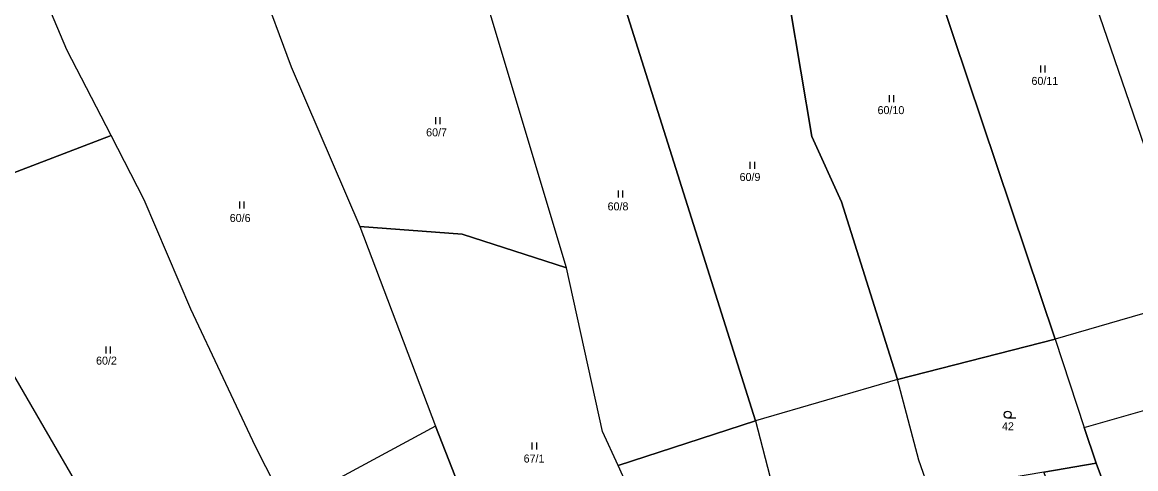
# Model space of a CAD drawing. Extents: x -590606 to -587796, y -1065936 to -1062515.
# Drawn here: x -588986.8 to -588750.2, y -1063771.4 to -1063676.6 of the extents above; entities that cross this region are included whole.
import ezdxf

# ---------------------------------------------------------------- set-up
doc = ezdxf.new("R2010")
doc.units = 0
doc.layers.add('Parcela nároku', color=7, linetype='Continuous')
doc.layers.add('Vrstva 30', color=7, linetype='Continuous')

msp = doc.modelspace()

# ---------------------------------------------------------------- linework, layer by layer
at = {"layer": 'Parcela nároku'}
for points in [[(-588715.88, -1063703.75), (-588717.17, -1063701.02), (-588727.07, -1063668.38), (-588735.7, -1063635.44), (-588736.61, -1063632.84), (-588745.65, -1063607.09), (-588774.83, -1063620.01), (-588765.6, -1063642.45), (-588759.52, -1063670.62), (-588737.36, -1063735.2), (-588707.2, -1063726.47), (-588707.58, -1063725.52)], [(-588759.52, -1063670.62), (-588737.36, -1063735.2), (-588767.37, -1063743.88), (-588804.55, -1063633.17), (-588774.83, -1063620.01), (-588765.6, -1063642.45)], [(-588804.55, -1063633.17), (-588767.37, -1063743.88), (-588800.86, -1063752.46), (-588812.73, -1063714.74), (-588819.04, -1063700.9), (-588823.74, -1063673.11), (-588832.46, -1063645.53)], [(-588819.04, -1063700.9), (-588812.73, -1063714.74), (-588800.86, -1063752.46), (-588831.03, -1063761.24), (-588863.26, -1063659.16), (-588832.46, -1063645.53), (-588823.74, -1063673.11)], [(-588889.43, -1063667.78), (-588894.21, -1063655.69), (-588891.16, -1063668.92), (-588910.08, -1063673.49), (-588936.37, -1063667.89), (-588929.67, -1063686.07), (-588915.05, -1063719.98), (-588893.31, -1063721.6), (-588871.15, -1063728.75), (-588888.64, -1063670.4)], [(-588967.9, -1063700.67), (-588977.28, -1063682.45), (-588988.07, -1063656.88), (-589019.8, -1063682.85), (-589006.06, -1063715.24)], [(-588915.05, -1063719.98), (-588898.96, -1063762.41), (-588930.68, -1063779.51), (-588937.25, -1063766.73), (-588950.98, -1063737.57), (-588960.87, -1063714.33), (-588967.9, -1063700.67), (-588977.28, -1063682.45), (-588988.07, -1063656.88), (-588936.37, -1063667.89), (-588929.67, -1063686.07)], [(-588863.26, -1063659.16), (-588831.03, -1063761.24), (-588860.18, -1063770.74), (-588863.5, -1063763.51), (-588871.15, -1063728.75), (-588888.64, -1063670.4)], [(-589006.06, -1063715.24), (-588995.94, -1063739.11), (-588960.84, -1063799.54), (-588989.02, -1063819.29), (-588994.94, -1063811.86), (-589006.48, -1063793.6), (-589024.66, -1063772.58), (-589046.9, -1063728.25), (-589051.16, -1063720.8), (-589037.08, -1063705.89), (-589019.8, -1063682.85)], [(-588930.68, -1063779.51), (-588937.25, -1063766.73), (-588950.98, -1063737.57), (-588960.87, -1063714.33), (-588967.9, -1063700.67), (-589006.06, -1063715.24), (-588995.94, -1063739.11), (-588960.84, -1063799.54)], [(-588871.15, -1063728.75), (-588893.31, -1063721.6), (-588915.05, -1063719.98), (-588898.96, -1063762.41), (-588878.03, -1063815.85), (-588873.66, -1063826.25), (-588869.66, -1063824.08), (-588850.19, -1063817.93), (-588845.55, -1063816.47), (-588848.39, -1063808.69), (-588844.85, -1063807.93), (-588849.19, -1063795.07), (-588860.18, -1063770.74), (-588863.5, -1063763.51)], [(-588735.67, -1063739.15), (-588737.36, -1063735.2), (-588767.37, -1063743.88), (-588761.16, -1063762.69), (-588730.44, -1063753.9)], [(-588800.86, -1063752.46), (-588767.37, -1063743.88), (-588761.16, -1063762.69), (-588758.63, -1063770.24), (-588769.77, -1063772.13), (-588793.94, -1063776.29), (-588796.33, -1063769.6)], [(-588785.9, -1063800.35), (-588793.94, -1063776.29), (-588796.33, -1063769.6), (-588800.86, -1063752.46), (-588831.03, -1063761.24), (-588827.44, -1063774.96), (-588824.49, -1063774.65), (-588813.22, -1063812.04), (-588806.34, -1063827.54), (-588788.52, -1063820.38), (-588778.65, -1063817.94), (-588779.46, -1063816.73), (-588783.24, -1063799.73)], [(-588721.81, -1063775.15), (-588717.46, -1063785.01), (-588714.57, -1063790.47), (-588717.31, -1063791.84), (-588746.33, -1063803.42), (-588758.63, -1063770.24), (-588761.16, -1063762.69), (-588730.44, -1063753.9)], [(-588898.96, -1063762.41), (-588930.68, -1063779.51), (-588911.22, -1063809.98), (-588903.58, -1063826.39), (-588900.04, -1063836.93), (-588894.8, -1063827.31), (-588890.55, -1063825.59), (-588878.03, -1063815.85)], [(-588860.18, -1063770.74), (-588831.03, -1063761.24), (-588827.44, -1063774.96), (-588824.84, -1063784.42), (-588849.19, -1063795.07)], [(-588769.77, -1063772.13), (-588758.63, -1063770.24), (-588746.33, -1063803.42), (-588742.66, -1063812.78), (-588752.9, -1063815.09), (-588755.96, -1063807.29)]]:
    msp.add_lwpolyline(points, close=True, dxfattribs=at)
at = {"layer": 'Vrstva 30'}
for p, q in [((-588770.5, -1063685.8), (-588770.5, -1063687.3)), ((-588769.47, -1063687.3), (-588769.47, -1063685.8)), ((-588802.64, -1063692.06), (-588802.64, -1063693.56)), ((-588801.61, -1063693.56), (-588801.61, -1063692.06)), ((-588899.01, -1063696.78), (-588899.01, -1063698.28)), ((-588897.98, -1063698.28), (-588897.98, -1063696.78)), ((-588832.2, -1063706.26), (-588832.2, -1063707.76)), ((-588831.18, -1063707.76), (-588831.18, -1063706.26)), ((-588860.18, -1063712.35), (-588860.18, -1063713.85)), ((-588859.16, -1063713.85), (-588859.16, -1063712.35)), ((-588940.66, -1063714.66), (-588940.66, -1063716.16)), ((-588939.64, -1063716.16), (-588939.64, -1063714.66)), ((-588969.03, -1063745.47), (-588969.03, -1063746.97)), ((-588968.01, -1063746.97), (-588968.01, -1063745.47)), ((-588775.7, -1063760.7), (-588777.45, -1063760.7)), ((-588878.49, -1063765.88), (-588878.49, -1063767.38)), ((-588877.46, -1063767.38), (-588877.46, -1063765.88))]:
    msp.add_line(p, q, dxfattribs=at)
msp.add_circle((-588777.45, -1063759.95), 0.75, dxfattribs=at)

# ---------------------------------------------------------------- texts
at = {"layer": 'Parcela nároku'}
for s, p in [('60/11', (-588772.38, -1063689.91)), ('60/10', (-588805.08, -1063696.11)), ('60/7', (-588900.98, -1063700.83)), ('60/9', (-588834.39, -1063710.31)), ('60/8', (-588862.43, -1063716.56)), ('60/6', (-588942.7, -1063719.02)), ('60/2', (-588971.1, -1063749.32)), ('42', (-588778.65, -1063763.27)), ('67/1', (-588880.27, -1063770.12))]:
    msp.add_text(s, height=1.7, dxfattribs=at).set_placement(p)

doc.saveas('drawing.dxf')
